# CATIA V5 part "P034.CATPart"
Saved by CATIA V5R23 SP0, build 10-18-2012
Part number: P034
Definition: Entretoise du galet
Description: Entretoise du galet
Bounding box of the stored display mesh (mm): x -12 to 12, y -3.25 to 3.25, z -12 to 12
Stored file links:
  C:\wamp\www\COURS\CONCEPTION GMP1\TITRE 02-SEMESTRE 2\03-TP7-PRESSE MECANIQUE\eleve\P034.CATPart
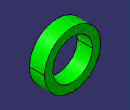
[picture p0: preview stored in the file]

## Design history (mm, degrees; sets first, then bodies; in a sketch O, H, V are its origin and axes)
Body1 (main body)
  Sketch1 on zx-plane, origin (0, 0, 0), H (-1, 0, 0), V (0, 0, 1)
    circle A1 centre (0, 0) radius 12
    circle A2 centre (0, 0) radius 8.5
    radius A1 = 12
    radius A2 = 8.5
  Pad1: profile Sketch1, direction (0, 1, 0), length 3.25, mirrored extent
